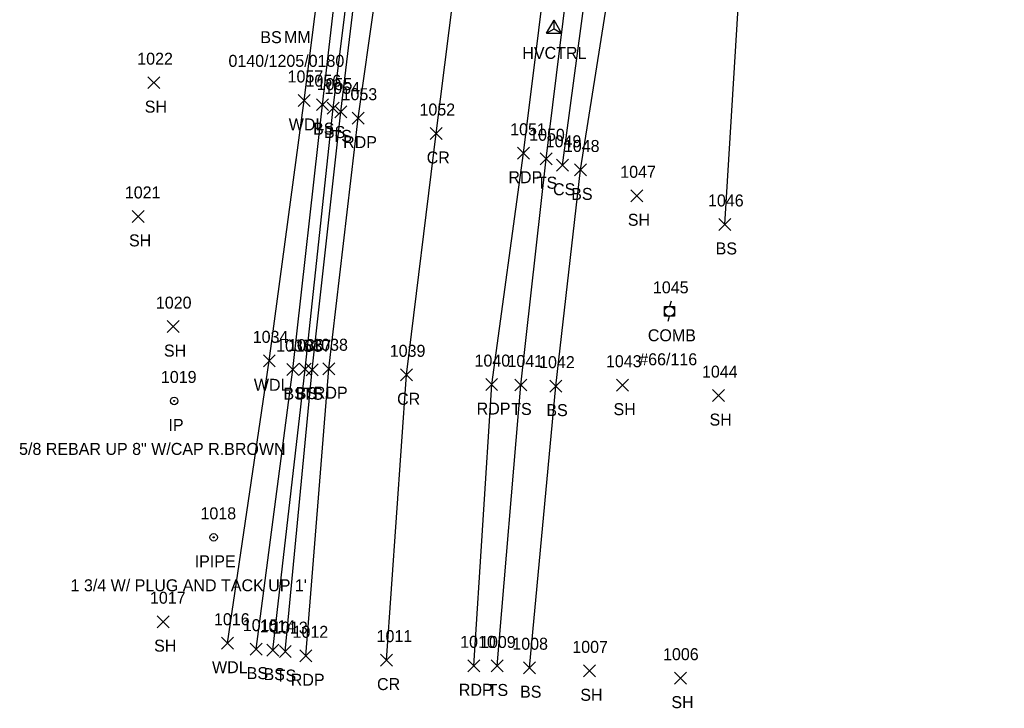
# Model space of a CAD drawing. Extents: x 1654425 to 1656893, y 667839 to 678429.
# Drawn here: x 1654453.2 to 1654617.5, y 667839.4 to 667954.2 of the extents above; entities that cross this region are included whole.
import ezdxf

# ---------------------------------------------------------------- set-up
doc = ezdxf.new("R2010")
doc.units = 0
for name, color, linetype in [('C_A', 7, 'Continuous'), ('CPSM', 7, 'Continuous'), ('L_A', 7, 'Continuous'), ('L_I', 7, 'Continuous'), ('L_TIC', 7, 'Continuous'), ('LAWA', 7, 'Continuous'), ('LELB', 7, 'Continuous'), ('M_A', 7, 'Continuous'), ('M_C', 7, 'Continuous'), ('M_I', 7, 'Continuous'), ('MPIP', 7, 'Continuous'), ('MPIR', 7, 'Continuous'), ('P_A', 7, 'Continuous'), ('P_I', 7, 'Continuous'), ('P_TIC', 7, 'Continuous'), ('PET', 7, 'Continuous'), ('PRC', 7, 'Continuous'), ('S_A', 7, 'Continuous'), ('S_C', 7, 'Continuous'), ('U_A', 7, 'Continuous'), ('U_C', 7, 'Continuous'), ('U_I', 7, 'Continuous'), ('UP', 7, 'Continuous')]:
    doc.layers.add(name, color=color, linetype=linetype)

msp = doc.modelspace()

# ---------------------------------------------------------------- linework, layer by layer
at = {"layer": 'CPSM'}
for p, q in [((1654541.14, 667951.99), (1654542.39, 667954.15)), ((1654543.64, 667951.99), (1654542.39, 667954.15)), ((1654542.39, 667952.71), (1654542.39, 667954.15)), ((1654541.14, 667951.99), (1654542.39, 667952.71)), ((1654542.39, 667952.71), (1654542.39, 667952.71)), ((1654542.39, 667952.71), (1654543.64, 667951.99)), ((1654541.14, 667951.99), (1654543.64, 667951.99))]:
    msp.add_line(p, q, dxfattribs=at)
at = {"layer": 'L_TIC'}
for points in [[(1654474.56, 667942.74), (1654476.56, 667944.74)], [(1654476.56, 667942.74), (1654474.56, 667944.74)], [(1654499.67, 667939.77), (1654501.67, 667941.77)], [(1654501.67, 667939.77), (1654499.67, 667941.77)], [(1654502.7, 667939.07), (1654504.7, 667941.07)], [(1654504.7, 667939.07), (1654502.7, 667941.07)], [(1654504.52, 667938.5), (1654506.52, 667940.5)], [(1654506.52, 667938.5), (1654504.52, 667940.5)], [(1654505.8, 667937.86), (1654507.8, 667939.86)], [(1654507.8, 667937.86), (1654505.8, 667939.86)], [(1654540.08, 667930.05), (1654542.08, 667932.05)], [(1654542.08, 667930.05), (1654540.08, 667932.05)], [(1654542.76, 667928.96), (1654544.76, 667930.96)], [(1654544.76, 667928.96), (1654542.76, 667930.96)], [(1654545.8, 667928.18), (1654547.8, 667930.18)], [(1654547.8, 667928.18), (1654545.8, 667930.18)], [(1654555.2, 667923.87), (1654557.2, 667925.87)], [(1654557.2, 667923.87), (1654555.2, 667925.87)], [(1654471.92, 667920.43), (1654473.92, 667922.43)], [(1654473.92, 667920.43), (1654471.92, 667922.43)], [(1654569.91, 667919.09), (1654571.91, 667921.09)], [(1654571.91, 667919.09), (1654569.91, 667921.09)], [(1654477.76, 667902.05), (1654479.76, 667904.05)], [(1654479.76, 667902.05), (1654477.76, 667904.05)], [(1654493.84, 667896.34), (1654495.84, 667898.34)], [(1654495.84, 667896.34), (1654493.84, 667898.34)], [(1654497.76, 667894.88), (1654499.76, 667896.88)], [(1654499.76, 667894.88), (1654497.76, 667896.88)], [(1654499.81, 667894.96), (1654501.81, 667896.96)], [(1654501.81, 667894.96), (1654499.81, 667896.96)], [(1654500.99, 667894.85), (1654502.99, 667896.85)], [(1654502.99, 667894.85), (1654500.99, 667896.85)], [(1654535.81, 667892.31), (1654537.81, 667894.31)], [(1654537.81, 667892.31), (1654535.81, 667894.31)], [(1654541.65, 667892.12), (1654543.65, 667894.12)], [(1654543.65, 667892.12), (1654541.65, 667894.12)], [(1654552.81, 667892.28), (1654554.81, 667894.28)], [(1654554.81, 667892.28), (1654552.81, 667894.28)], [(1654568.84, 667890.54), (1654570.84, 667892.54)], [(1654570.84, 667890.54), (1654568.84, 667892.54)], [(1654476.12, 667852.83), (1654478.12, 667854.83)], [(1654478.12, 667852.83), (1654476.12, 667854.83)], [(1654486.86, 667849.24), (1654488.86, 667851.24)], [(1654488.86, 667849.24), (1654486.86, 667851.24)], [(1654491.62, 667848.25), (1654493.62, 667850.25)], [(1654493.62, 667848.25), (1654491.62, 667850.25)], [(1654494.43, 667848.08), (1654496.43, 667850.08)], [(1654496.43, 667848.08), (1654494.43, 667850.08)], [(1654496.51, 667847.84), (1654498.51, 667849.84)], [(1654498.51, 667847.84), (1654496.51, 667849.84)], [(1654531.88, 667845.44), (1654533.88, 667847.44)], [(1654533.88, 667845.44), (1654531.88, 667847.44)], [(1654537.26, 667845.15), (1654539.26, 667847.15)], [(1654539.26, 667845.15), (1654537.26, 667847.15)], [(1654547.27, 667844.63), (1654549.27, 667846.63)], [(1654549.27, 667844.63), (1654547.27, 667846.63)], [(1654562.47, 667843.41), (1654564.47, 667845.41)], [(1654564.47, 667843.41), (1654562.47, 667845.41)]]:
    msp.add_lwpolyline(points, dxfattribs=at)
at = {"layer": 'LAWA'}
msp.add_lwpolyline([(1654487.86, 667850.24), (1654494.84, 667897.34), (1654500.67, 667940.77), (1654505.51, 667978.89), (1654509.61, 668019.56), (1654510.39, 668046.1), (1654508.8, 668074.55), (1654512.45, 668081.46), (1654516.35, 668119.35), (1654498.68, 668136.06), (1654489.89, 668151.28)], dxfattribs=at)
at = {"layer": 'LELB'}
for points in [[(1654495.43, 667849.08), (1654500.81, 667895.96), (1654505.52, 667939.5), (1654510.36, 667978.52), (1654516.04, 668017.45), (1654520.13, 668047.02), (1654521.8, 668078.81), (1654520.96, 668117.25), (1654511.8, 668137.4), (1654509.93, 668148.4), (1654514.52, 668176.02), (1654523.2, 668207.52), (1654535.05, 668244.08), (1654541.09, 668271.34), (1654546.04, 668295.57), (1654553.44, 668325.52), (1654559.28, 668346.56), (1654565.49, 668358.45)], [(1654497.51, 667848.84), (1654501.99, 667895.85), (1654506.8, 667938.86), (1654511.52, 667978.38), (1654518.04, 668017.75), (1654522.23, 668046.7), (1654527.11, 668078.6), (1654529.66, 668139.05), (1654535.37, 668180.01), (1654543.78, 668219.73), (1654556.62, 668268.25), (1654562.63, 668297.63), (1654565.24, 668311.03), (1654570.38, 668336.59), (1654576.33, 668345.51)], [(1654532.88, 667846.44), (1654536.81, 667893.31), (1654541.08, 667931.05), (1654546.18, 667972.49), (1654551.95, 668011.91), (1654556.54, 668041.44), (1654561.5, 668072.5), (1654571.11, 668129.18), (1654578.93, 668172.43), (1654586.94, 668211.68), (1654595.67, 668254.34), (1654607.41, 668286.92), (1654610.93, 668292.61), (1654617.54, 668318.12), (1654616.79, 668336.32)], [(1654543.76, 667929.96), (1654549.41, 667971.89), (1654554.38, 668011.7), (1654559.28, 668041.03), (1654563.69, 668071.7), (1654573.34, 668128.44), (1654581.87, 668172.56), (1654590.31, 668210.74), (1654599.29, 668252.88), (1654609.98, 668283.91), (1654610.93, 668292.61)], [(1654538.26, 667846.15), (1654542.65, 667893.12), (1654546.8, 667929.18), (1654553.5, 667971.67), (1654558.51, 668011.64), (1654562.47, 668041.03), (1654569.65, 668073.66), (1654578.54, 668087.47), (1654583.04, 668117.51)], [(1654492.62, 667849.25), (1654498.76, 667895.88), (1654503.7, 667940.07), (1654508.18, 667978.57), (1654513.8, 668018.14), (1654517.68, 668047.52), (1654517.89, 668074.98), (1654512.45, 668081.46), (1654487.26, 668098.75)], [(1654570.91, 667920.09), (1654573.84, 667968.01), (1654576.77, 668008.9), (1654586.57, 668040.61), (1654581.49, 668071.6), (1654578.54, 668087.47)]]:
    msp.add_lwpolyline(points, dxfattribs=at)
at = {"layer": 'MPIP'}
for radius in [0.625, 0.0833]:
    msp.add_circle((1654485.55, 667867.9), radius, dxfattribs=at)
at = {"layer": 'MPIR'}
for radius in [0.625, 0.0833]:
    msp.add_circle((1654478.95, 667890.65), radius, dxfattribs=at)
at = {"layer": 'P_TIC'}
for points in [[(1654508.67, 667936.82), (1654510.67, 667938.82)], [(1654510.67, 667936.82), (1654508.67, 667938.82)], [(1654521.68, 667934.26), (1654523.68, 667936.26)], [(1654523.68, 667934.26), (1654521.68, 667936.26)], [(1654536.26, 667930.97), (1654538.26, 667932.97)], [(1654538.26, 667930.97), (1654536.26, 667932.97)], [(1654503.78, 667895.02), (1654505.78, 667897.02)], [(1654505.78, 667895.02), (1654503.78, 667897.02)], [(1654516.73, 667894.01), (1654518.73, 667896.01)], [(1654518.73, 667894.01), (1654516.73, 667896.01)], [(1654530.96, 667892.38), (1654532.96, 667894.38)], [(1654532.96, 667892.38), (1654530.96, 667894.38)], [(1654499.93, 667847.14), (1654501.93, 667849.14)], [(1654501.93, 667847.14), (1654499.93, 667849.14)], [(1654513.39, 667846.42), (1654515.39, 667848.42)], [(1654515.39, 667846.42), (1654513.39, 667848.42)], [(1654527.99, 667845.47), (1654529.99, 667847.47)], [(1654529.99, 667845.47), (1654527.99, 667847.47)]]:
    msp.add_lwpolyline(points, dxfattribs=at)
at = {"layer": 'PET'}
for points in [[(1654500.93, 667848.14), (1654504.78, 667896.02), (1654509.67, 667937.82), (1654515.37, 667977.68), (1654521.39, 668016.85), (1654525.99, 668046.3), (1654531.26, 668078.24), (1654541.38, 668136.51), (1654548.54, 668178.15), (1654556.41, 668219.5), (1654564.06, 668264.06), (1654572.07, 668308.08), (1654579.91, 668345.23), (1654595.42, 668341.51), (1654611.88, 668337.75)], [(1654528.99, 667846.47), (1654531.96, 667893.38), (1654537.26, 667931.97), (1654542.41, 667973.09), (1654548.22, 668012.23), (1654553.01, 668041.79), (1654558.55, 668073.69), (1654568.05, 668129.99), (1654575.97, 668172.91), (1654583.21, 668212.31), (1654592.64, 668255.65), (1654604.22, 668302.74), (1654611.88, 668337.75)]]:
    msp.add_lwpolyline(points, dxfattribs=at)
at = {"layer": 'PRC'}
msp.add_lwpolyline([(1654514.39, 667847.42), (1654517.73, 667895.01), (1654522.68, 667935.26), (1654527.79, 667975.85), (1654533.53, 668014.87), (1654538.36, 668044.09), (1654543.94, 668076.54), (1654553.86, 668133.31), (1654561.61, 668175.74), (1654568.95, 668214.62), (1654577.86, 668259.83), (1654587.68, 668305.21), (1654595.42, 668341.51)], dxfattribs=at)
at = {"layer": 'UP'}
for p, q in [((1654560.81, 667904.77), (1654560.81, 667906.43)), ((1654560.81, 667906.43), (1654562.48, 667906.43)), ((1654561.9, 667907.27), (1654561.65, 667906.43)), ((1654562.48, 667906.43), (1654562.48, 667904.77)), ((1654562.48, 667904.77), (1654560.81, 667904.77)), ((1654561.4, 667903.93), (1654561.65, 667904.77)), ((1654561.65, 667905.6), (1654561.65, 667905.6))]:
    msp.add_line(p, q, dxfattribs=at)
msp.add_circle((1654561.65, 667905.6), 0.833, dxfattribs=at)

# ---------------------------------------------------------------- texts
at = {"layer": 'C_A'}
msp.add_text('HVCTRL', height=2, dxfattribs=at).set_placement((1654537.08, 667947.71))
at = {"layer": 'L_A'}
for s, p in [('BS', (1654493.34, 667950.33)), ('SH', (1654474.04, 667938.74)), ('WDL', (1654498.08, 667935.77)), ('BS', (1654502.14, 667935.07)), ('BS', (1654503.96, 667934.5)), ('TS', (1654505.21, 667933.86)), ('TS', (1654539.49, 667926.05)), ('CS', (1654542.2, 667924.96)), ('BS', (1654545.24, 667924.18)), ('SH', (1654554.69, 667919.87)), ('SH', (1654471.41, 667916.43)), ('BS', (1654569.35, 667915.09)), ('SH', (1654477.24, 667898.05)), ('WDL', (1654492.26, 667892.34)), ('BS', (1654497.2, 667890.88)), ('BS', (1654499.25, 667890.96)), ('TS', (1654500.4, 667890.85)), ('TS', (1654535.22, 667888.31)), ('BS', (1654541.09, 667888.12)), ('SH', (1654552.3, 667888.28)), ('SH', (1654568.33, 667886.54)), ('SH', (1654475.61, 667848.83)), ('WDL', (1654485.27, 667845.24)), ('BS', (1654491.06, 667844.25)), ('BS', (1654493.87, 667844.08)), ('TS', (1654495.91, 667843.84)), ('TS', (1654531.29, 667841.44)), ('BS', (1654536.7, 667841.15)), ('SH', (1654546.76, 667840.63)), ('SH', (1654561.96, 667839.41))]:
    msp.add_text(s, height=2, dxfattribs=at).set_placement(p)
at = {"layer": 'L_I'}
for s, p in [('1022', (1654472.79, 667946.74)), ('1057', (1654497.89, 667943.77)), ('1056', (1654500.88, 667943.07)), ('1055', (1654502.75, 667942.5)), ('1054', (1654504.03, 667941.86)), ('1050', (1654538.22, 667934.05)), ('1049', (1654540.98, 667932.96)), ('1048', (1654544.02, 667932.18)), ('1047', (1654553.43, 667927.87)), ('1021', (1654470.72, 667924.43)), ('1046', (1654568.08, 667923.09)), ('1020', (1654475.9, 667906.05)), ('1034', (1654492.07, 667900.34)), ('1035', (1654495.98, 667898.88)), ('1036', (1654497.98, 667898.96)), ('1037', (1654499.22, 667898.85)), ('1041', (1654534.6, 667896.31)), ('1042', (1654539.88, 667896.12)), ('1043', (1654551.04, 667896.28)), ('1044', (1654567.07, 667894.54)), ('1017', (1654474.91, 667856.83)), ('1016', (1654485.6, 667853.24)), ('1015', (1654490.41, 667852.25)), ('1014', (1654493.22, 667852.08)), ('1013', (1654495.3, 667851.84)), ('1009', (1654530.02, 667849.44)), ('1008', (1654535.41, 667849.15)), ('1007', (1654545.42, 667848.63)), ('1006', (1654560.57, 667847.41))]:
    msp.add_text(s, height=2, dxfattribs=at).set_placement(p)
at = {"layer": 'M_A'}
for s, p in [('IP', (1654478, 667885.65)), ('IPIPE', (1654482.38, 667862.9))]:
    msp.add_text(s, height=2, dxfattribs=at).set_placement(p)
at = {"layer": 'M_C'}
for s, p in [('5/8 REBAR UP 8" W/CAP R.BROWN', (1654453.06, 667881.65)), ("1 3/4 W/ PLUG AND TACK UP 1'", (1654461.66, 667858.9))]:
    msp.add_text(s, height=2, dxfattribs=at).set_placement(p)
at = {"layer": 'M_I'}
for s, p in [('1019', (1654476.74, 667893.65)), ('1018', (1654483.35, 667870.9))]:
    msp.add_text(s, height=2, dxfattribs=at).set_placement(p)
at = {"layer": 'P_A'}
for s, p in [('RDP', (1654507.16, 667932.82)), ('CR', (1654521.11, 667930.26)), ('RDP', (1654534.75, 667926.97)), ('RDP', (1654502.27, 667891.02)), ('CR', (1654516.17, 667890.01)), ('RDP', (1654529.45, 667888.38)), ('RDP', (1654498.42, 667843.14)), ('CR', (1654512.82, 667842.42)), ('RDP', (1654526.48, 667841.47))]:
    msp.add_text(s, height=2, dxfattribs=at).set_placement(p)
at = {"layer": 'P_I'}
for s, p in [('1053', (1654506.9, 667940.82)), ('1052', (1654519.91, 667938.26)), ('1051', (1654535.05, 667934.97)), ('1038', (1654502.01, 667899.02)), ('1039', (1654514.95, 667898.01)), ('1040', (1654529.1, 667896.38)), ('1012', (1654498.72, 667851.14)), ('1011', (1654512.75, 667850.42)), ('1010', (1654526.7, 667849.47))]:
    msp.add_text(s, height=2, dxfattribs=at).set_placement(p)
at = {"layer": 'S_A'}
msp.add_text('MM', height=2, dxfattribs=at).set_placement((1654497.3, 667950.38))
at = {"layer": 'S_C'}
msp.add_text('0140/1205/0180', height=2, dxfattribs=at).set_placement((1654488.02, 667946.38))
at = {"layer": 'U_A'}
msp.add_text('COMB', height=2, dxfattribs=at).set_placement((1654558.03, 667900.6))
at = {"layer": 'U_C'}
msp.add_text('#66/116', height=2, dxfattribs=at).set_placement((1654556.6, 667896.6))
at = {"layer": 'U_I'}
msp.add_text('1045', height=2, dxfattribs=at).set_placement((1654558.88, 667908.6))

doc.saveas('drawing.dxf')
